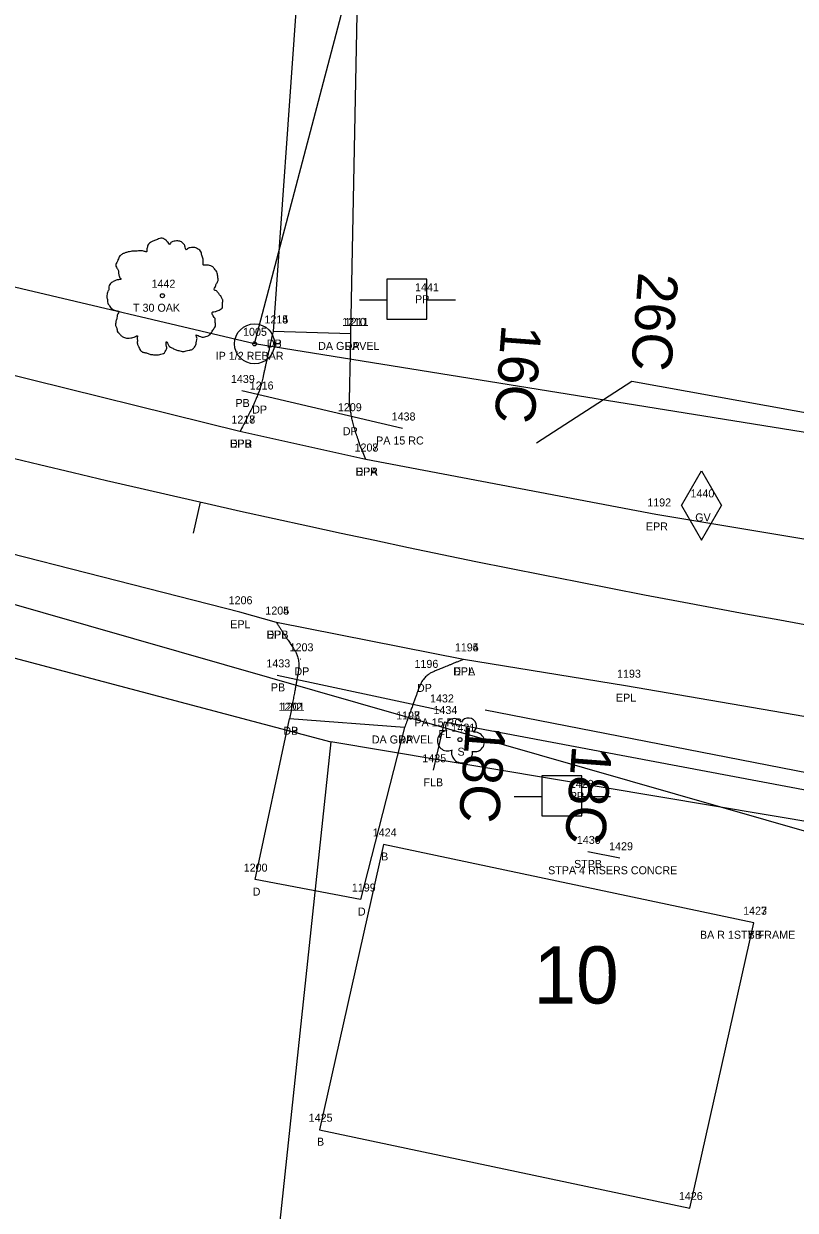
# Model space of a CAD drawing. Extents: x 1812113 to 1819860, y 1177290 to 1181185.
# Drawn here: x 1813371.7 to 1813468, y 1178709.1 to 1178857.4 of the extents above; entities that cross this region are included whole.
import ezdxf

# ---------------------------------------------------------------- set-up
doc = ezdxf.new("R2010")
doc.units = 0
for name, color, linetype in [('RD_EX_Bldg', 7, 'Continuous'), ('RD_EX_Bldg_txCode', 7, 'Continuous'), ('RD_EX_Conc', 7, 'Continuous'), ('RD_EX_Conc_txCode', 7, 'Continuous'), ('RD_EX_DR_Pipe', 7, 'Continuous'), ('RD_EX_DR_Pipe_txCode', 7, 'Continuous'), ('RD_EX_Driveway', 7, 'Continuous'), ('RD_EX_Driveway_txCode', 7, 'Continuous'), ('RD_EX_DV_Prop', 7, 'Continuous'), ('RD_EX_DV_Prop_txCode', 7, 'Continuous'), ('RD_EX_DV_PropPin', 7, 'Continuous'), ('RD_EX_DV_TX_Prop', 7, 'Continuous'), ('RD_EX_Fence_Other', 7, 'Continuous'), ('RD_EX_Fence_Other_txCode', 7, 'Continuous'), ('RD_EX_Road', 7, 'Continuous'), ('RD_EX_Road_txCode', 7, 'Continuous'), ('RD_EX_RW', 7, 'Continuous'), ('RD_EX_UT', 7, 'Continuous'), ('RD_EX_UT_txCode', 7, 'Continuous'), ('RD_EX_VEG', 7, 'Continuous'), ('RD_EX_VEG_txCode', 7, 'Continuous'), ('RD_HC_CL', 7, 'Continuous'), ('RD_HC_Data_Tic', 7, 'Continuous'), ('RD_PD_CstnLmt', 7, 'Continuous'), ('RD_SMD_Locator', 7, 'Continuous')]:
    doc.layers.add(name, color=color, linetype=linetype)

msp = doc.modelspace()

# ---------------------------------------------------------------- linework, layer by layer
at = {"layer": 'RD_EX_Bldg'}
msp.add_lwpolyline([(1813462.81, 1178745.04), (1813416.58, 1178754.82), (1813408.58, 1178719.18), (1813454.82, 1178709.39), (1813462.81, 1178745.04)], dxfattribs=at)
at = {"layer": 'RD_EX_Conc'}
msp.add_line((1813446.08, 1178753.1), (1813442.1, 1178753.89), dxfattribs=at)
at = {"layer": 'RD_EX_DR_Pipe'}
for p, q in [((1813418.94, 1178806.8), (1813398.87, 1178811.49)), ((1813423.73, 1178771.57), (1813403.29, 1178775.95))]:
    msp.add_line(p, q, dxfattribs=at)
at = {"layer": 'RD_EX_Driveway'}
for p, q in [((1813405.99, 1178863.99), (1813402.78, 1178818.92)), ((1813412.51, 1178818.62), (1813413.38, 1178863.09)), ((1813412.51, 1178818.62), (1813402.78, 1178818.92)), ((1813419.21, 1178769.44), (1813404.84, 1178770.53))]:
    msp.add_line(p, q, dxfattribs=at)
msp.add_lwpolyline([(1813419.21, 1178769.44), (1813413.68, 1178747.94), (1813400.54, 1178750.43), (1813404.84, 1178770.53)], dxfattribs=at)
for points in [[(1813402.78, 1178818.92), (1813401.87, 1178814.8), (1813400.96, 1178810.67), (1813398.64, 1178806.42)], [(1813414.35, 1178802.92), (1813412.27, 1178807.96), (1813412.39, 1178813.29), (1813412.51, 1178818.62)], [(1813403.21, 1178782.55), (1813404.72, 1178780.25), (1813406.23, 1178777.96), (1813405.54, 1178774.24), (1813404.84, 1178770.53)], [(1813426.54, 1178777.95), (1813424.03, 1178776.92), (1813421.53, 1178775.89), (1813420.37, 1178772.67), (1813419.21, 1178769.44)]]:
    msp.add_open_spline(points, degree=2, dxfattribs=at)
at = {"layer": 'RD_EX_DV_Prop'}
for p, q in [((1813400.47, 1178817.38), (1813428.23, 1178922.79)), ((1813409.98, 1178767.65), (1813396.08, 1178636.38))]:
    msp.add_line(p, q, dxfattribs=at)
at = {"layer": 'RD_EX_DV_PropPin'}
for radius in [2.5, 0.25]:
    msp.add_circle((1813400.47, 1178817.38), radius, dxfattribs=at)
at = {"layer": 'RD_EX_Fence_Other'}
msp.add_lwpolyline([(1813499.51, 1178755.92), (1813424.16, 1178770.12), (1813422.76, 1178764.09)], dxfattribs=at)
at = {"layer": 'RD_EX_Road'}
for p, q in [((1813398.64, 1178806.42), (1813355.44, 1178817.13)), ((1813414.35, 1178802.92), (1813398.64, 1178806.42)), ((1813450.56, 1178796.06), (1813414.35, 1178802.92)), ((1813499.47, 1178787.87), (1813450.56, 1178796.06))]:
    msp.add_line(p, q, dxfattribs=at)
msp.add_lwpolyline([(1813732.94, 1178707.95), (1813689.88, 1178731.75), (1813641.71, 1178744.36), (1813593.37, 1178752.09), (1813544.49, 1178758.77), (1813495.45, 1178766.29), (1813446.8, 1178774.66), (1813426.54, 1178777.95), (1813403.21, 1178782.55), (1813398.65, 1178783.84), (1813350.68, 1178796.09), (1813343.23, 1178797.92), (1813318.7, 1178804.23), (1813303.26, 1178808.85), (1813256.8, 1178823.17), (1813209.81, 1178838.91), (1813163.27, 1178855.57)], dxfattribs=at)
at = {"layer": 'RD_EX_RW'}
for p, q in [((1813400.47, 1178817.38), (1813327.69, 1178834.58)), ((1813632.03, 1178780.07), (1813400.47, 1178817.38)), ((1813275.15, 1178803.43), (1813409.98, 1178767.65)), ((1813539.17, 1178745.92), (1813409.98, 1178767.65))]:
    msp.add_line(p, q, dxfattribs=at)
at = {"layer": 'RD_EX_UT'}
for p, q in [((1813422, 1178825.46), (1813417, 1178825.46)), ((1813417, 1178825.46), (1813417, 1178820.46)), ((1813422, 1178820.46), (1813422, 1178825.46)), ((1813413.57, 1178822.89), (1813417.04, 1178822.89)), ((1813421.93, 1178822.89), (1813425.57, 1178822.89)), ((1813417, 1178820.46), (1813422, 1178820.46)), ((1813453.78, 1178797.19), (1813456.28, 1178801.52)), ((1813456.28, 1178801.52), (1813458.78, 1178797.19)), ((1813453.78, 1178797.19), (1813456.28, 1178792.86)), ((1813456.28, 1178792.86), (1813458.78, 1178797.19)), ((1813441.32, 1178763.4), (1813436.32, 1178763.4)), ((1813436.32, 1178763.4), (1813436.32, 1178758.4)), ((1813441.32, 1178758.4), (1813441.32, 1178763.4)), ((1813432.89, 1178760.83), (1813436.36, 1178760.83)), ((1813441.25, 1178760.83), (1813444.89, 1178760.83)), ((1813436.32, 1178758.4), (1813441.32, 1178758.4))]:
    msp.add_line(p, q, dxfattribs=at)
msp.add_lwpolyline([(1812996.89, 1178919.95), (1813204.49, 1178832.44), (1813481.3, 1178753.03), (1813490.2, 1178706.76)], dxfattribs=at)
at = {"layer": 'RD_EX_VEG'}
for centre, radius in [((1813388.96, 1178823.39), 0.25), ((1813388.95, 1178823.37), 0.0001), ((1813426.12, 1178767.92), 0.25)]:
    msp.add_circle(centre, radius, dxfattribs=at)
for centre, radius, start, end in [((1813427.17, 1178769.63), 0.995, 308.7626, 152.0467), ((1813425.4, 1178769.47), 1.08, 34.9763, 204.756), ((1813424.56, 1178767.77), 1.26, 96.4518, 294.734), ((1813427.96, 1178767.64), 1.22, 256.5667, 98.1046), ((1813426.37, 1178766.33), 1.32, 166.8827, 5.7589)]:
    msp.add_arc(centre, radius, start, end, dxfattribs=at)
for points in [[(1813389.09, 1178830.56), (1813388.79, 1178830.58), (1813388.47, 1178830.48), (1813388.22, 1178830.38), (1813387.99, 1178830.31), (1813387.77, 1178830.21), (1813387.47, 1178830.03), (1813387.24, 1178829.83), (1813387.12, 1178829.58), (1813387.07, 1178829.36), (1813387.02, 1178829.09), (1813387.02, 1178828.91), (1813386.89, 1178828.89), (1813386.74, 1178828.91), (1813386.49, 1178828.99), (1813386.24, 1178828.99), (1813385.99, 1178828.99), (1813385.64, 1178828.96), (1813385.29, 1178828.96), (1813385.02, 1178828.91), (1813384.69, 1178828.86), (1813384.32, 1178828.74), (1813383.97, 1178828.61), (1813383.67, 1178828.36), (1813383.42, 1178827.89), (1813383.29, 1178827.54), (1813383.14, 1178827.29), (1813383.29, 1178826.84), (1813383.47, 1178826.49), (1813383.49, 1178826.29), (1813383.57, 1178825.86), (1813383.67, 1178825.64), (1813383.79, 1178825.44), (1813383.72, 1178825.41), (1813383.34, 1178825.36), (1813383.04, 1178825.26), (1813382.62, 1178825.04), (1813382.39, 1178824.81), (1813382.29, 1178824.49), (1813382.27, 1178824.14), (1813382.17, 1178823.94), (1813382.09, 1178823.66), (1813382.07, 1178823.59), (1813382.02, 1178823.26), (1813382.12, 1178822.81), (1813382.14, 1178822.46), (1813382.27, 1178822.24), (1813382.42, 1178822.06), (1813382.59, 1178821.81), (1813382.99, 1178821.59), (1813383.32, 1178821.49), (1813383.52, 1178821.46), (1813383.34, 1178820.96), (1813383.29, 1178820.61), (1813383.17, 1178820.21), (1813383.17, 1178820.14), (1813383.12, 1178819.66), (1813383.27, 1178819.34), (1813383.34, 1178818.96), (1813383.52, 1178818.74), (1813383.79, 1178818.44), (1813384.12, 1178818.21), (1813384.62, 1178818.09), (1813385.02, 1178818.11), (1813385.59, 1178818.29), (1813385.84, 1178818.36), (1813385.82, 1178818.19), (1813385.84, 1178817.81), (1813385.84, 1178817.39), (1813385.99, 1178817.07), (1813386.09, 1178816.79), (1813386.24, 1178816.54), (1813386.57, 1178816.32), (1813386.97, 1178816.24), (1813387.39, 1178816.09), (1813387.84, 1178816.02), (1813388.34, 1178815.99), (1813388.94, 1178816.14), (1813389.22, 1178816.27), (1813389.32, 1178816.44), (1813389.52, 1178816.82), (1813389.47, 1178817.04), (1813389.49, 1178817.64), (1813389.59, 1178817.47), (1813389.77, 1178817.12), (1813390.27, 1178816.82), (1813390.67, 1178816.64), (1813391.14, 1178816.49), (1813391.44, 1178816.42), (1813391.92, 1178816.49), (1813392.29, 1178816.57), (1813392.67, 1178816.69), (1813392.97, 1178816.97), (1813393.14, 1178817.24), (1813393.19, 1178817.52), (1813393.26, 1178817.89), (1813393.31, 1178818.06)], [(1813393.31, 1178818.06), (1813393.24, 1178818.24), (1813393.19, 1178818.49), (1813393.26, 1178818.46), (1813393.44, 1178818.41), (1813393.71, 1178818.29), (1813393.94, 1178818.21), (1813394.26, 1178818.24), (1813394.54, 1178818.34), (1813394.99, 1178818.61), (1813395.26, 1178819.09), (1813395.54, 1178819.49), (1813395.61, 1178819.81), (1813395.56, 1178820.04), (1813395.54, 1178820.54), (1813395.34, 1178820.79), (1813395.29, 1178820.91), (1813395.19, 1178821.31), (1813395.26, 1178821.36), (1813395.54, 1178821.41), (1813395.91, 1178821.54), (1813396.19, 1178821.66), (1813396.41, 1178821.84), (1813396.49, 1178822.06), (1813396.46, 1178822.46), (1813396.51, 1178822.86), (1813396.44, 1178823.01), (1813396.34, 1178823.16), (1813396.26, 1178823.36), (1813396.11, 1178823.51), (1813396.01, 1178823.66), (1813395.91, 1178823.76), (1813395.79, 1178823.91), (1813395.61, 1178824.04), (1813395.46, 1178824.09), (1813395.41, 1178824.24), (1813395.56, 1178824.44), (1813395.61, 1178824.54), (1813395.64, 1178824.76), (1813395.86, 1178825.11), (1813395.91, 1178825.51), (1813395.86, 1178825.94), (1813395.81, 1178826.21), (1813395.66, 1178826.49), (1813395.46, 1178826.74), (1813395.34, 1178826.91), (1813395.16, 1178827.04), (1813394.84, 1178827.16), (1813394.59, 1178827.21), (1813394.24, 1178827.21), (1813394.04, 1178827.26), (1813394.06, 1178827.31), (1813394.06, 1178827.46), (1813394.06, 1178827.74), (1813393.99, 1178828.19), (1813393.84, 1178828.69), (1813393.84, 1178828.71), (1813393.74, 1178828.96), (1813393.51, 1178829.16), (1813393.34, 1178829.26), (1813393.14, 1178829.38), (1813392.89, 1178829.41), (1813392.59, 1178829.41), (1813392.32, 1178829.36), (1813392.12, 1178829.26), (1813391.94, 1178829.13), (1813391.87, 1178829.28), (1813391.77, 1178829.58), (1813391.72, 1178829.73), (1813391.57, 1178829.91), (1813391.34, 1178830.11), (1813390.89, 1178830.23), (1813390.27, 1178830.16), (1813389.97, 1178829.96), (1813389.82, 1178829.78), (1813389.77, 1178829.91), (1813389.57, 1178830.11), (1813389.47, 1178830.28), (1813389.29, 1178830.41), (1813389.14, 1178830.51), (1813389.04, 1178830.56)]]:
    msp.add_spline(points, degree=3, dxfattribs=at)
at = {"layer": 'RD_HC_CL'}
msp.add_arc((1813766.93, 1180445.18), 1689.31, 243.58271, 262.2191, dxfattribs=at)
at = {"layer": 'RD_HC_Data_Tic'}
msp.add_line((1813393.7, 1178797.61), (1813392.81, 1178793.71), dxfattribs=at)
at = {"layer": 'RD_PD_CstnLmt'}
for p, q in [((1813447.58, 1178812.68), (1813435.68, 1178804.98)), ((1813496.03, 1178803.9), (1813447.58, 1178812.68)), ((1813538.44, 1178750.29), (1813429.25, 1178771.59))]:
    msp.add_line(p, q, dxfattribs=at)
at = {"layer": 'RD_SMD_Locator'}
for centre in [(1813402.78, 1178818.92), (1813402.78, 1178818.92), (1813412.51, 1178818.62), (1813412.51, 1178818.62), (1813398.87, 1178811.49), (1813400.96, 1178810.67), (1813412.27, 1178807.96), (1813398.64, 1178806.42), (1813398.64, 1178806.42), (1813418.94, 1178806.8), (1813414.35, 1178802.92), (1813414.35, 1178802.92), (1813450.56, 1178796.06), (1813398.65, 1178783.84), (1813403.21, 1178782.55), (1813403.21, 1178782.55), (1813406.23, 1178777.96), (1813426.54, 1178777.95), (1813426.54, 1178777.95), (1813403.29, 1178775.95), (1813421.53, 1178775.89), (1813446.8, 1178774.66), (1813423.73, 1178771.57), (1813404.84, 1178770.53), (1813404.84, 1178770.53), (1813419.21, 1178769.44), (1813419.21, 1178769.44), (1813424.16, 1178770.12), (1813422.76, 1178764.09), (1813416.58, 1178754.82), (1813442.1, 1178753.89), (1813446.08, 1178753.1), (1813400.54, 1178750.43), (1813413.68, 1178747.94), (1813462.81, 1178745.04), (1813462.81, 1178745.04), (1813408.58, 1178719.18), (1813454.82, 1178709.39)]:
    msp.add_circle(centre, 0.001, dxfattribs=at)

# ---------------------------------------------------------------- texts
at = {"layer": 'RD_EX_Bldg_txCode'}
for s, p in [('1424', (1813415.23, 1178755.82)), ('B', (1813416.27, 1178752.82)), ('1423', (1813461.47, 1178746.04)), ('1427', (1813461.47, 1178746.04)), ('BA R 1STY FRAME', (1813456.08, 1178743.04)), ('BB', (1813462.03, 1178743.04)), ('1425', (1813407.23, 1178720.18)), ('B', (1813408.27, 1178717.18)), ('1426', (1813453.45, 1178710.39))]:
    msp.add_text(s, height=1, dxfattribs=at).set_placement(p)
at = {"layer": 'RD_EX_Conc_txCode'}
for s, p in [('1430', (1813440.71, 1178754.89)), ('1429', (1813444.74, 1178754.1)), ('STPB', (1813440.36, 1178751.89)), ('STPA 4 RISERS CONCRE', (1813437.12, 1178751.1))]:
    msp.add_text(s, height=1, dxfattribs=at).set_placement(p)
at = {"layer": 'RD_EX_DR_Pipe_txCode'}
for s, p in [('1439', (1813397.52, 1178812.49)), ('PB', (1813398.09, 1178809.49)), ('1438', (1813417.59, 1178807.8)), ('PA 15 RC', (1813415.65, 1178804.8)), ('1433', (1813401.95, 1178776.95)), ('PB', (1813402.51, 1178773.95)), ('1432', (1813422.38, 1178772.57)), ('PA 15 RC', (1813420.43, 1178769.57))]:
    msp.add_text(s, height=1, dxfattribs=at).set_placement(p)
at = {"layer": 'RD_EX_Driveway_txCode'}
for s, p in [('1214', (1813401.71, 1178819.92)), ('1215', (1813401.71, 1178819.92)), ('1210', (1813411.41, 1178819.62)), ('1211', (1813411.73, 1178819.62)), ('DB', (1813402, 1178816.92)), ('DP', (1813402, 1178816.92)), ('DA GRAVEL', (1813408.41, 1178816.62)), ('DP', (1813411.73, 1178816.62)), ('1216', (1813399.87, 1178811.67)), ('DP', (1813400.18, 1178808.67)), ('1209', (1813410.88, 1178808.96)), ('1217', (1813397.58, 1178807.42)), ('DP', (1813411.49, 1178805.96)), ('DPB', (1813397.39, 1178804.42)), ('1208', (1813412.96, 1178803.92)), ('DPA', (1813413.08, 1178800.92)), ('1204', (1813401.82, 1178783.55)), ('DPB', (1813401.96, 1178780.55)), ('1203', (1813404.85, 1178778.96)), ('1195', (1813425.48, 1178778.95)), ('DP', (1813405.45, 1178775.96)), ('1196', (1813420.44, 1178776.89)), ('DPA', (1813425.27, 1178775.95)), ('DP', (1813420.75, 1178773.89)), ('1202', (1813403.46, 1178771.53)), ('1201', (1813403.74, 1178771.53)), ('1197', (1813418.15, 1178770.44)), ('1198', (1813418.15, 1178770.44)), ('DB', (1813404.06, 1178768.53)), ('DP', (1813404.06, 1178768.53)), ('DA GRAVEL', (1813415.11, 1178767.44)), ('DP', (1813418.43, 1178767.44)), ('1200', (1813399.12, 1178751.43)), ('1199', (1813412.62, 1178748.94)), ('D', (1813400.24, 1178748.43)), ('D', (1813413.37, 1178745.94))]:
    msp.add_text(s, height=1, dxfattribs=at).set_placement(p)
at = {"layer": 'RD_EX_DV_Prop_txCode'}
for s, p in [('1005', (1813399.04, 1178818.38)), ('IP 1/2 REBAR', (1813395.62, 1178815.38))]:
    msp.add_text(s, height=1, dxfattribs=at).set_placement(p)
at = {"layer": 'RD_EX_DV_TX_Prop'}
msp.add_text('10', height=7.14, dxfattribs=at).set_placement((1813435.31, 1178734.95))
at = {"layer": 'RD_EX_Fence_Other_txCode'}
for s, p in [('1434', (1813422.81, 1178771.12)), ('FL', (1813423.43, 1178768.12)), ('1435', (1813421.42, 1178765.09)), ('FLB', (1813421.56, 1178762.09))]:
    msp.add_text(s, height=1, dxfattribs=at).set_placement(p)
at = {"layer": 'RD_EX_Road_txCode'}
for s, p in [('1218', (1813397.58, 1178807.42)), ('EPR', (1813397.42, 1178804.42)), ('1207', (1813412.96, 1178803.92)), ('EPR', (1813413.12, 1178800.92)), ('1192', (1813449.5, 1178797.06)), ('EPR', (1813449.33, 1178794.06)), ('1206', (1813397.24, 1178784.84)), ('1205', (1813401.82, 1178783.55)), ('EPL', (1813397.44, 1178781.84)), ('EPL', (1813402, 1178780.55)), ('1194', (1813425.48, 1178778.95)), ('EPL', (1813425.34, 1178775.95)), ('1193', (1813445.73, 1178775.66)), ('EPL', (1813445.59, 1178772.66))]:
    msp.add_text(s, height=1, dxfattribs=at).set_placement(p)
at = {"layer": 'RD_EX_UT_txCode'}
for s, p in [('1441', (1813420.51, 1178823.95)), ('PP', (1813420.51, 1178822.45)), ('1440', (1813454.9, 1178798.19)), ('GV', (1813455.49, 1178795.19)), ('1428', (1813439.83, 1178761.89)), ('PP', (1813439.83, 1178760.39))]:
    msp.add_text(s, height=1, dxfattribs=at).set_placement(p)
at = {"layer": 'RD_EX_VEG_txCode'}
for s, p in [('1442', (1813387.61, 1178824.39)), ('T 30 OAK', (1813385.3, 1178821.39)), ('1431', (1813425.06, 1178768.92)), ('S', (1813425.81, 1178765.92))]:
    msp.add_text(s, height=1, dxfattribs=at).set_placement(p)
at = {"layer": 'RD_PD_CstnLmt'}
for s, p in [('26C', (1813448.4, 1178826.4)), ('16C', (1813431.33, 1178819.87)), ('18C', (1813426.88, 1178769.94)), ('18C', (1813440.13, 1178767.27))]:
    msp.add_text(s, height=5, rotation=265.7319, dxfattribs=at).set_placement(p)

doc.saveas('drawing.dxf')
